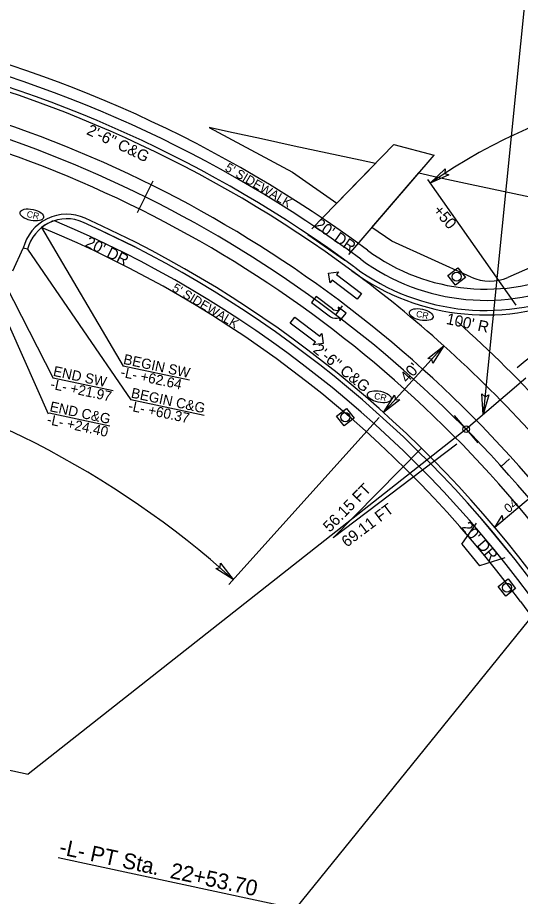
# Model space of a CAD drawing. Extents: x 1762196 to 1766326, y 709922 to 713142.
# Drawn here: x 1763113.4 to 1763337.1, y 712228.7 to 712620.3 of the extents above; entities that cross this region are included whole.
import ezdxf

# ---------------------------------------------------------------- set-up
doc = ezdxf.new("R2010")
doc.units = 0
for name, color, linetype in [('COGO Default Chain', 7, 'Continuous'), ('Default', 7, 'Continuous'), ('Old_Level_3', 7, 'Continuous'), ('Old_Level_30', 7, 'Continuous'), ('Pattern 1', 7, 'Continuous'), ('Pattern 2', 7, 'Continuous'), ('Pattern 4', 7, 'Continuous'), ('Pattern 5', 7, 'Continuous'), ('Prop Conc 2ft 6in Curb and Gutter', 7, 'Continuous'), ('Prop Dimension', 7, 'Continuous'), ('Prop EOT', 7, 'Continuous'), ('Prop Horizontal Alignment', 7, 'Continuous'), ('Prop Horizontal Alignment Station Label', 7, 'Continuous'), ('Prop Horizontal Alignment Tick Large', 7, 'Continuous'), ('Prop Horizontal Alignment Tick Small', 7, 'Continuous'), ('Prop Lane Arrow CELL', 7, 'Continuous'), ('Prop Lane Lines', 7, 'Continuous'), ('Prop Superelevation  Arrow CELL', 7, 'Continuous'), ('Prop Superelevation Label', 7, 'Continuous'), ('Prop Terminator CELL', 7, 'Continuous')]:
    doc.layers.add(name, color=color, linetype=linetype)

msp = doc.modelspace()

# ---------------------------------------------------------------- linework, layer by layer
at = {"layer": 'COGO Default Chain'}
for p, q in [((1763198.66, 712571.24), (1763235.64, 712551.43)), ((1763199.1, 712571), (1763199.18, 712571.05)), ((1763255.47, 712537.6), (1763272.59, 712555.21)), ((1763235.64, 712551.43), (1763255.47, 712537.6)), ((1763271.05, 712526.74), (1763291.92, 712551.05)), ((1763279.82, 712520.62), (1763271.05, 712526.74)), ((1763315.25, 712504.61), (1763279.82, 712520.62))]:
    msp.add_line(p, q, dxfattribs=at)
for points in [[(1763272.59, 712555.21), (1763265.79, 712556.74), (1763251.15, 712559.89), (1763236.51, 712563.03), (1763221.89, 712566.22), (1763207.24, 712569.34), (1763198.66, 712571.24)], [(1763291.92, 712551.05), (1763300.15, 712549.23)], [(1763300.15, 712549.23), (1763314.78, 712546.01), (1763329.45, 712542.98), (1763344.08, 712539.74), (1763351.23, 712538.32)], [(1763368.2, 712534.57), (1763359.78, 712516.93), (1763331.53, 712504.52)]]:
    msp.add_lwpolyline(points, dxfattribs=at)
msp.add_arc((1763323.49, 712522.84), 20, 245.6803, 293.7138, dxfattribs=at)
at = {"layer": 'Default'}
for points in [[(1763312.6, 712504.41), (1763308.25, 712501.01), (1763304.84, 712505.36), (1763309.2, 712508.77)], [(1763263.06, 712441.8), (1763258.71, 712438.39), (1763255.3, 712442.75), (1763259.66, 712446.15)], [(1763334.99, 712365.86), (1763330.63, 712362.46), (1763327.23, 712366.81), (1763331.59, 712370.21)]]:
    msp.add_lwpolyline(points, close=True, dxfattribs=at)
for centre in [(1763308.7, 712504.84), (1763259.16, 712442.23), (1763331.09, 712366.29)]:
    msp.add_circle(centre, 2.03, dxfattribs=at)
at = {"layer": 'Old_Level_3'}
for p, q in [((1763244.3, 712526.13), (1763280.82, 712563.67)), ((1763280.82, 712563.67), (1763298.66, 712558.9)), ((1763260.7, 712514.68), (1763298.66, 712558.9)), ((1763310.99, 712385.69), (1763317.49, 712395.07)), ((1763310.99, 712385.69), (1763318.96, 712376.07)), ((1763330.24, 712379.61), (1763318.96, 712376.07))]:
    msp.add_line(p, q, dxfattribs=at)
at = {"layer": 'Old_Level_30'}
for p in [(1763308.76, 712430.21), (1763293.13, 712428.4)]:
    msp.add_line(p, (1763253.72, 712388.41), dxfattribs=at)
at = {"layer": 'Pattern 1'}
msp.add_line((1763337.1, 712360.07), (1763843.84, 711670.85), dxfattribs=at)
for centre, radius, start, end in [((1762933.05, 712063), 564.5, 53.4772, 77.7598), ((1762933.05, 712063), 559.5, 53.4772, 77.7598), ((1763135.27, 712512.62), 18, 107.8812, 128.5238), ((1762933.05, 712063), 506.5, 36.325, 67.1495), ((1762933.05, 712063), 501.5, 36.325, 67.6128), ((1763321.68, 712587.77), 88.5, 233.4772, 295.722), ((1763321.68, 712587.77), 93.5, 233.4772, 295.722)]:
    msp.add_arc(centre, radius, start, end, dxfattribs=at)
at = {"layer": 'Pattern 2'}
for centre, radius, start, end in [((1762933.05, 712063), 564.5, 53.4772, 77.7598), ((1762933.05, 712063), 559.5, 53.4772, 77.7598), ((1762933.05, 712063), 506.5, 36.325, 67.1495), ((1762933.05, 712063), 501.5, 36.325, 67.6128), ((1763321.68, 712587.77), 88.5, 233.4772, 295.722), ((1763321.68, 712587.77), 93.5, 233.4772, 295.722)]:
    msp.add_arc(centre, radius, start, end, dxfattribs=at)
at = {"layer": 'Pattern 4'}
for p, q in [((1763165.62, 712517.94), (1763147.58, 712526.72)), ((1763242.59, 712523.67), (1763258.98, 712512.22)), ((1763332.56, 712381.52), (1763319.81, 712396.98))]:
    msp.add_line(p, q, dxfattribs=at)
at = {"layer": 'Pattern 5'}
for centre in [(1763119.72, 712532.35), (1763292.98, 712487.92), (1763274.33, 712451.34)]:
    msp.add_ellipse(centre, major_axis=(5.26, -1.13), ratio=0.462467, dxfattribs=at)
at = {"layer": 'Prop Conc 2ft 6in Curb and Gutter'}
msp.add_line((1763117.81, 712517.02), (1763115.87, 712517.5), dxfattribs=at)
for centre, radius, start, end in [((1762933.05, 712063), 555, 53.4772, 77.7598), ((1763135.27, 712512.62), 18, 65.7844, 165.8723), ((1762933.05, 712063), 511, 36.325, 65.7844), ((1763321.68, 712587.77), 98, 233.4772, 295.722)]:
    msp.add_arc(centre, radius, start, end, dxfattribs=at)
at = {"layer": 'Prop Dimension'}
for p, q in [((1763295.81, 712548.11), (1763335.04, 712492.13)), ((1763088.15, 712539.92), (1763129.2, 712459.66)), ((1763127.11, 712443.61), (1763087.8, 712531.55)), ((1763124.06, 712526.7), (1763160.42, 712464.99)), ((1763117.81, 712517.02), (1763163.76, 712449.99)), ((1763276.25, 712444.29), (1763303.01, 712474.02)), ((1763189.85, 712458.66), (1763160.42, 712464.99)), ((1763155.86, 712453.93), (1763129.2, 712459.66)), ((1763196.46, 712442.96), (1763163.76, 712449.99)), ((1763154.42, 712438.29), (1763127.5, 712444.08)), ((1763207.35, 712367.74), (1763274.25, 712442.06))]:
    msp.add_line(p, q, dxfattribs=at)
for centre, radius, start, end in [((1763439.73, 712342.72), 248.79, 77.9589, 125.0188), ((1762933.05, 712063), 413, 48.0096, 77.7598)]:
    msp.add_arc(centre, radius, start, end, dxfattribs=at)
at = {"layer": 'Prop EOT'}
msp.add_line((1763111.29, 712507.5), (1763115.87, 712517.5), dxfattribs=at)
for centre, radius, start, end in [((1762933.05, 712063), 553, 53.4772, 77.7598), ((1763135.27, 712512.62), 20, 65.7844, 165.8723), ((1762933.05, 712063), 513, 36.325, 65.7844), ((1763321.68, 712587.77), 100, 233.4772, 295.722)]:
    msp.add_arc(centre, radius, start, end, dxfattribs=at)
at = {"layer": 'Prop Horizontal Alignment'}
msp.add_line((1763339.51, 712459.65), (1763312.94, 712436.87), dxfattribs=at)
msp.add_arc((1762933.05, 712063), 533, 36.325, 77.7598, dxfattribs=at)
at = {"layer": 'Prop Horizontal Alignment Station Label'}
for p, q in [((1763341.29, 712649.99), (1763320.6, 712443.44)), ((1763312.94, 712436.87), (1763118.09, 712283.17)), ((1763362.47, 712378.73), (1763237.09, 712223.4)), ((1763008.03, 712306.84), (1763118.09, 712283.17)), ((1763131.45, 712246.11), (1763237.09, 712223.4))]:
    msp.add_line(p, q, dxfattribs=at)
msp.add_circle((1763312.94, 712436.87), 1.5, dxfattribs=at)
at = {"layer": 'Prop Horizontal Alignment Tick Large'}
for p, q in [((1763170.07, 712540.4), (1763173.63, 712547.57)), ((1763170.07, 712540.4), (1763166.51, 712533.24)), ((1763312.94, 712436.87), (1763307.73, 712442.94)), ((1763312.94, 712436.87), (1763318.14, 712430.8))]:
    msp.add_line(p, q, dxfattribs=at)
at = {"layer": 'Prop Horizontal Alignment Tick Small'}
for p, q in [((1763254.96, 712487.82), (1763257.98, 712491.8)), ((1763328.54, 712420.32), (1763332.25, 712423.67))]:
    msp.add_line(p, q, dxfattribs=at)
at = {"layer": 'Prop Lane Arrow CELL'}
for p, q in [((1763251.77, 712506.4), (1763256.22, 712507.04)), ((1763252.4, 712502.02), (1763251.77, 712506.4)), ((1763256.22, 712507.04), (1763255.31, 712505.84)), ((1763253.31, 712503.22), (1763252.4, 712502.02)), ((1763264.45, 712494.74), (1763253.31, 712503.22)), ((1763255.31, 712505.84), (1763266.45, 712497.37)), ((1763246.2, 712495.98), (1763244.2, 712493.35)), ((1763253.48, 712490.44), (1763246.2, 712495.98)), ((1763266.45, 712497.37), (1763264.45, 712494.74)), ((1763244.2, 712493.35), (1763252.6, 712486.96)), ((1763259.52, 712488.55), (1763255.97, 712491.31)), ((1763255.97, 712491.31), (1763256.17, 712489.84)), ((1763234.73, 712484.1), (1763236.73, 712486.73)), ((1763236.73, 712486.73), (1763247.87, 712478.26)), ((1763256.62, 712486.55), (1763256.82, 712485.08)), ((1763256.82, 712485.08), (1763259.52, 712488.55)), ((1763245.87, 712475.63), (1763234.73, 712484.1)), ((1763247.87, 712478.26), (1763248.78, 712479.45)), ((1763248.78, 712479.45), (1763249.41, 712475.08)), ((1763244.96, 712474.44), (1763245.87, 712475.63)), ((1763249.41, 712475.08), (1763244.96, 712474.44))]:
    msp.add_line(p, q, dxfattribs=at)
for centre, radius, start, end in [((1763255.46, 712493.03), 3.27, 232.7481, 282.4063), ((1763255.1, 712491.56), 5.25, 241.4242, 286.7359)]:
    msp.add_arc(centre, radius, start, end, dxfattribs=at)
at = {"layer": 'Prop Lane Lines'}
for centre, radius, start, end in [((1762933.05, 712063), 539, 36.325, 77.7598), ((1762933.05, 712063), 527, 36.325, 77.7598), ((1762933.05, 712063), 553, 48.0096, 53.4772), ((1763439.73, 712342.72), 160, 77.9589, 130.6003), ((1762933.05, 712063), 565, 36.325, 48.2811), ((1762933.05, 712063), 553, 36.325, 48.0096)]:
    msp.add_arc(centre, radius, start, end, dxfattribs=at)
at = {"layer": 'Prop Superelevation  Arrow CELL'}
msp.add_lwpolyline([(1763325.74, 712393.11), (1763329.04, 712398.5), (1763329.28, 712396.08)], close=True, dxfattribs=at)
at = {"layer": 'Prop Superelevation Label'}
msp.add_line((1763365.54, 712426.57), (1763325.74, 712393.11), dxfattribs=at)
at = {"layer": 'Prop Terminator CELL'}
for points in [[(1763305.31, 712550.16), (1763296.96, 712546.47), (1763303.61, 712552.81), (1763303.54, 712550.84)], [(1763295.84, 712468.37), (1763303.01, 712474.02), (1763298.15, 712466.23), (1763297.73, 712468.15)], [(1763283.43, 712449.95), (1763276.25, 712444.29), (1763281.12, 712452.09), (1763281.54, 712450.16)], [(1763323.04, 712452.24), (1763320.6, 712443.44), (1763319.91, 712452.6), (1763321.39, 712451.3)], [(1763203.7, 712377.14), (1763209.35, 712369.97), (1763201.56, 712374.83), (1763203.48, 712375.25)]]:
    msp.add_lwpolyline(points, close=True, dxfattribs=at)

# ---------------------------------------------------------------- texts
at = {"layer": 'Old_Level_30'}
for s, rotation, p in [('56.15 FT', 45.4206, (1763252.28, 712390.7)), ('69.11 FT', 37.2126, (1763259.88, 712384.06))]:
    msp.add_text(s, height=5, rotation=rotation, dxfattribs=at).set_placement(p)
at = {"layer": 'Pattern 5'}
for p in [(1763117.21, 712531.44), (1763290.47, 712487.01), (1763271.82, 712450.43)]:
    msp.add_text('CR', height=2.88, rotation=347.8639, dxfattribs=at).set_placement(p)
at = {"layer": 'Prop Dimension'}
for s, height, rotation, p in [('2\'-6" C&G', 5, 334.43, (1763143.69, 712568.45)), ("5' SIDEWALK", 4, 329.4234, (1763205.28, 712552.34)), ('+50', 5, 310.6003, (1763297.95, 712534.15)), ("20' DR", 5, 325.0693, (1763245.05, 712527.06)), ("20' DR", 5, 333.7166, (1763143.09, 712518.5)), ("5' SIDEWALK", 4, 328.9883, (1763181.78, 712498.72)), ("100' R", 5, 347.8639, (1763303.8, 712483.81)), ('2\'-6" C&G', 5, 321.2505, (1763244.52, 712471.59)), ('BEGIN SW', 4.5, 347.8639, (1763160.14, 712466.02)), ('END SW', 4.5, 347.8639, (1763128.92, 712460.7)), ('-L- +62.64', 4.5, 347.8639, (1763158.91, 712460.3)), ("40'", 5, 48.0096, (1763286.75, 712457.17)), ('-L- +21.97', 4.5, 347.8639, (1763127.69, 712454.98)), ('BEGIN C&G', 4.5, 347.8639, (1763163.58, 712451.01)), ('END C&G', 4.5, 347.8639, (1763127.4, 712444.93)), ('-L- +60.37', 4.5, 347.8639, (1763162.35, 712445.29)), ('-L- +24.40', 4.5, 347.8639, (1763126.17, 712439.21)), ("20' DR", 5, 310.8259, (1763310.48, 712393.04))]:
    msp.add_text(s, height=height, rotation=rotation, dxfattribs=at).set_placement(p)
at = {"layer": 'Prop Horizontal Alignment Station Label'}
msp.add_text('-L- PT Sta.  22+53.70', height=7, rotation=347.8638, dxfattribs=at).set_placement((1763131.53, 712247.61))
at = {"layer": 'Prop Superelevation Label'}
msp.add_text('04', height=4, rotation=38.7997, dxfattribs=at).set_placement((1763331.83, 712399.36))

doc.saveas('drawing.dxf')
